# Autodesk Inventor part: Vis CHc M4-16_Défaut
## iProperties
Shininess: 64.0
Length Units: 11269
Angle Units: 11279
Time Units: 11290
Mass Units: 11283
Length Display Precision: 3
Angle Display Precision: 2
Compacted: True
Part Number: Vis CHc M4-16_Défaut
Document SubType Name: Modeling
Created: 2006-01
Material: Par défaut
Designer: Fricot
Density: 0.0
Volumn: 0.0
Area: 0.0
PropertySet Name: Model Information
Control State: 0
Master: False
Checked Out: False
Author: Fricot
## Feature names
1. Base1
